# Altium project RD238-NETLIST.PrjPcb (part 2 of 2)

## Sheet 15.SchDoc
size 420 x 297 mm
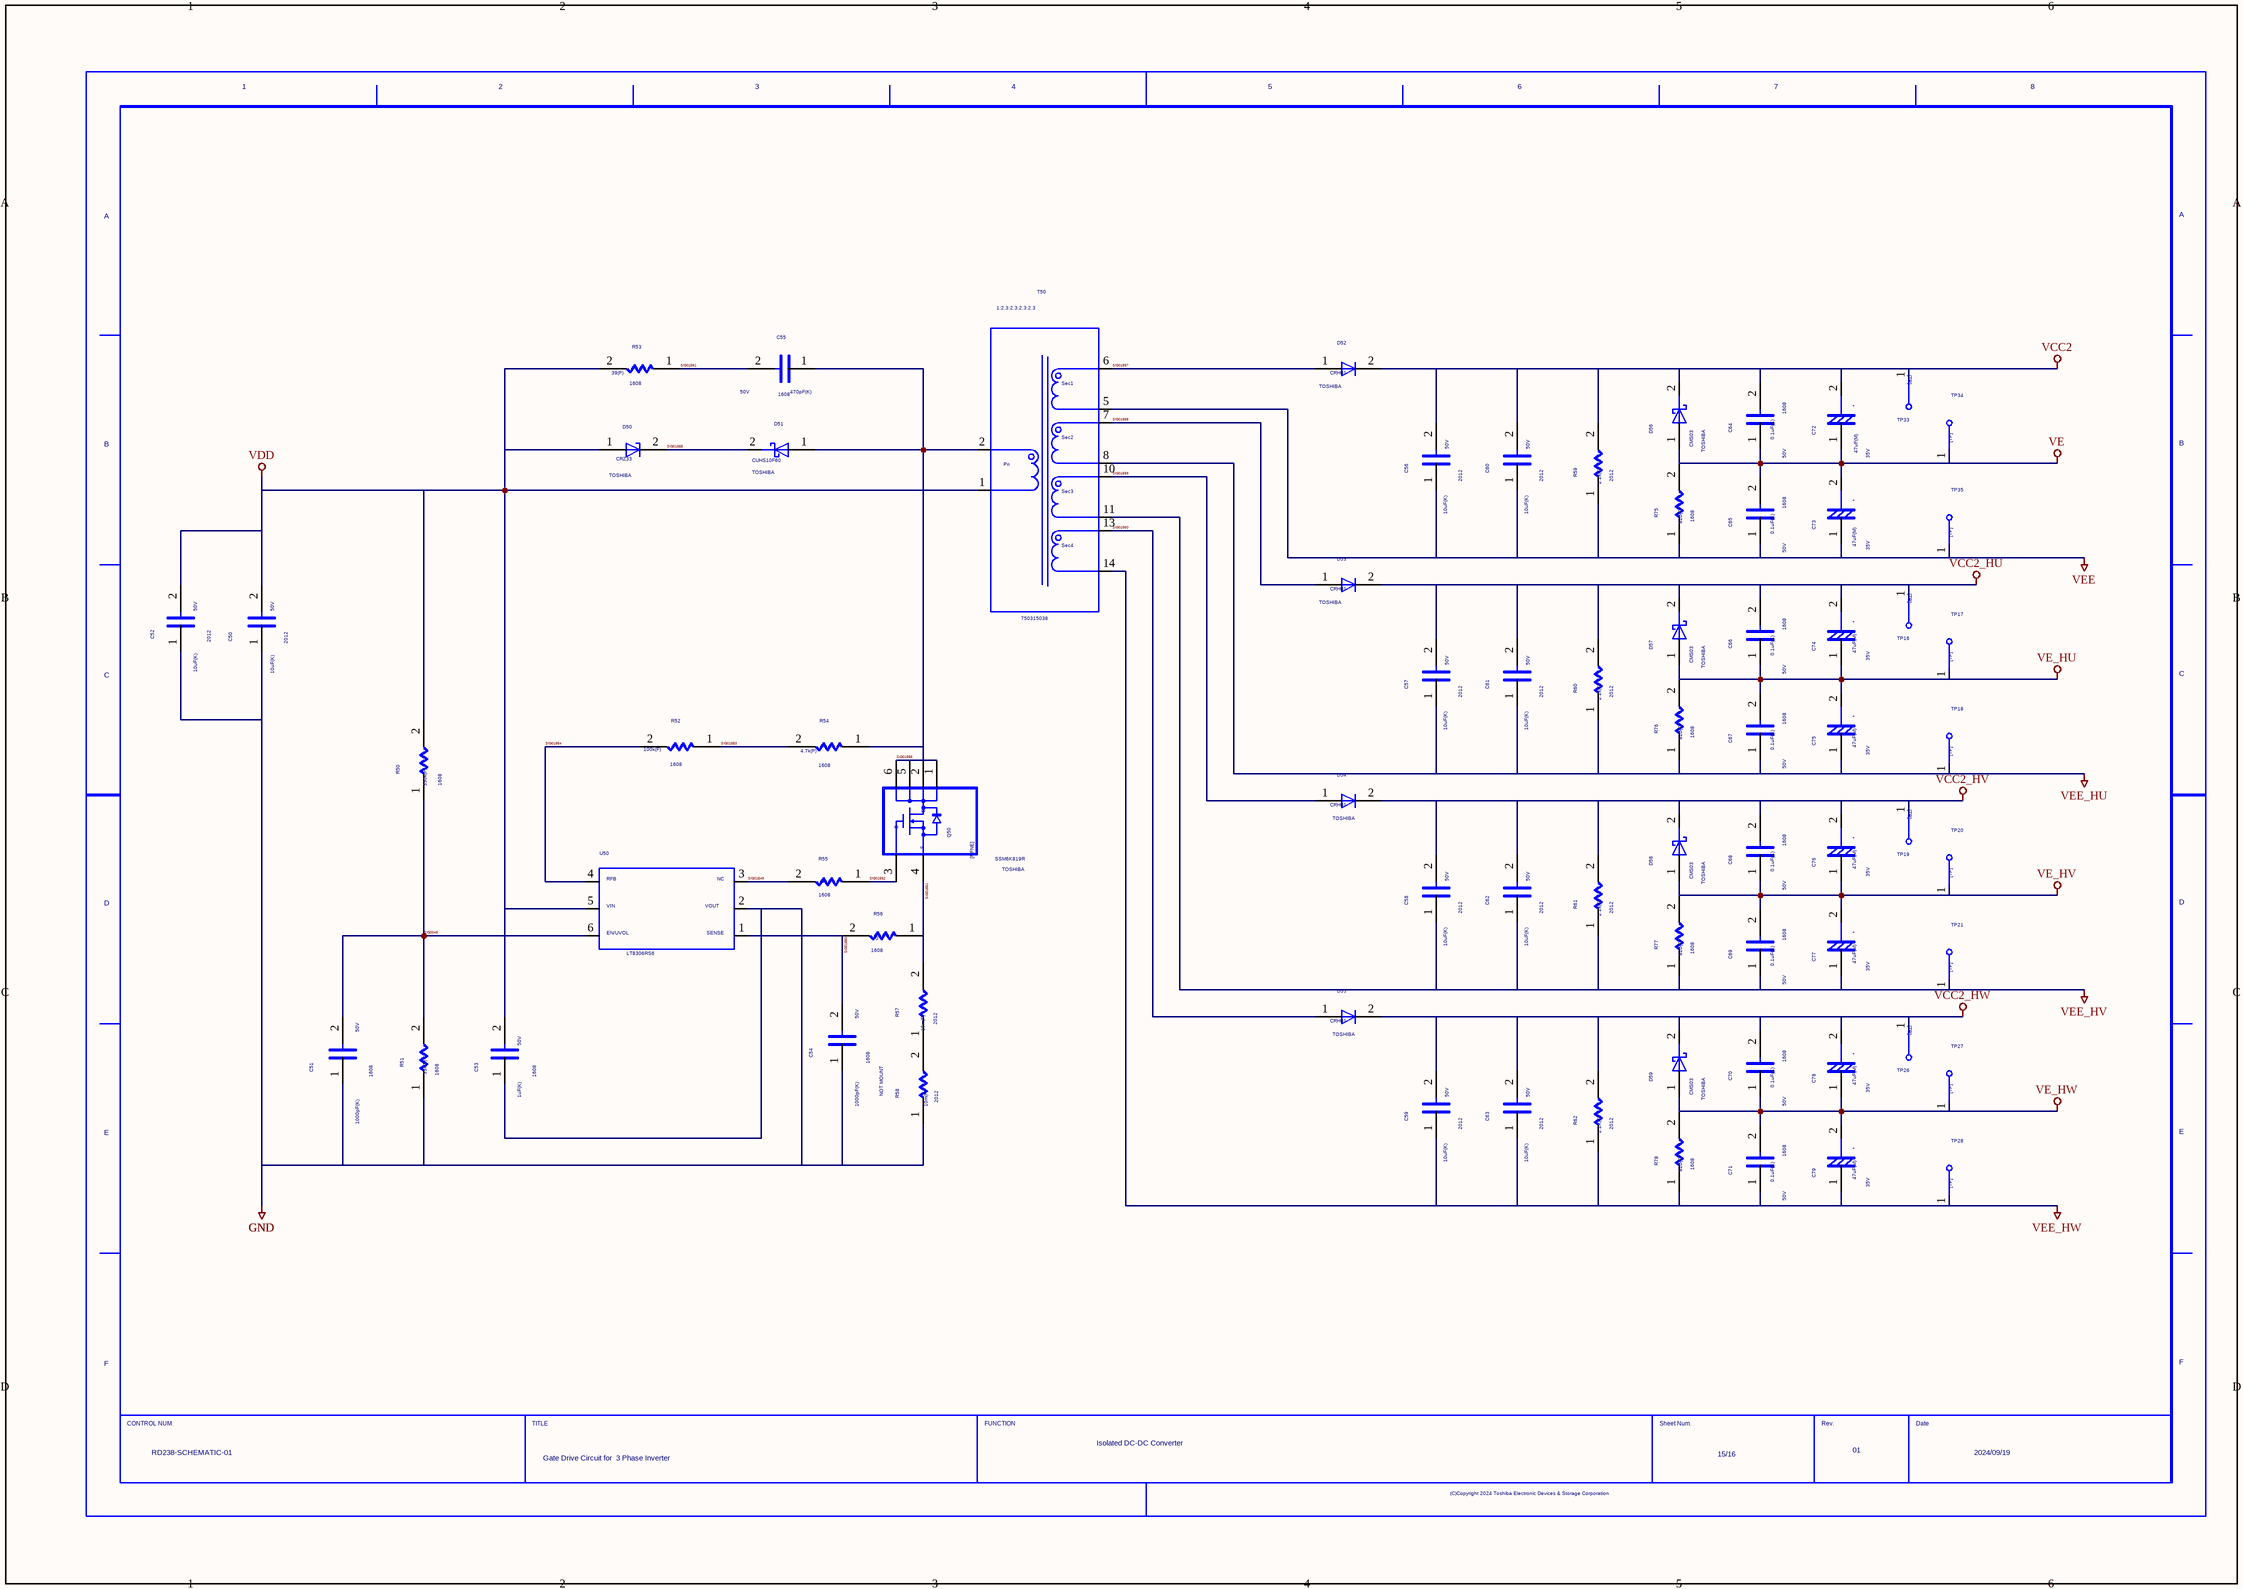
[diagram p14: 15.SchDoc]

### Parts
(Parts that share a designator on the sheet are numbered #1, #2 ... from top to bottom, then left to right.)
C50  VAL1: 10uF(K)  VAL2: 50V  SIZECODESMD: 2012  (hidden comment: C)
C51  VAL1: 1000pF(K)  VAL2: 50V  SIZECODESMD: 1608  (hidden comment: C)
C52  VAL1: 10uF(K)  VAL2: 50V  SIZECODESMD: 2012  (hidden comment: C)
C53  VAL1: 1uF(K)  VAL2: 50V  SIZECODESMD: 1608  (hidden comment: C)
C54  NOTMOUNT: NOT MOUNT  VAL1: 1000pF(K)  VAL2: 50V  SIZECODESMD: 1608  (hidden comment: C)
C55  VAL1: 470pF(K)  VAL2: 50V  SIZECODESMD: 1608  (hidden comment: C)
C56  VAL1: 10uF(K)  VAL2: 50V  SIZECODESMD: 2012  (hidden comment: C)
C57  VAL1: 10uF(K)  VAL2: 50V  SIZECODESMD: 2012  (hidden comment: C)
C58  VAL1: 10uF(K)  VAL2: 50V  SIZECODESMD: 2012  (hidden comment: C)
C59  VAL1: 10uF(K)  VAL2: 50V  SIZECODESMD: 2012  (hidden comment: C)
C60  VAL1: 10uF(K)  VAL2: 50V  SIZECODESMD: 2012  (hidden comment: C)
C61  VAL1: 10uF(K)  VAL2: 50V  SIZECODESMD: 2012  (hidden comment: C)
C62  VAL1: 10uF(K)  VAL2: 50V  SIZECODESMD: 2012  (hidden comment: C)
C63  VAL1: 10uF(K)  VAL2: 50V  SIZECODESMD: 2012  (hidden comment: C)
C64  VAL1: 0.1uF(K)  VAL2: 50V  SIZECODESMD: 1608  (hidden comment: C)
C65  VAL1: 0.1uF(K)  VAL2: 50V  SIZECODESMD: 1608  (hidden comment: C)
C66  VAL1: 0.1uF(K)  VAL2: 50V  SIZECODESMD: 1608  (hidden comment: C)
C67  VAL1: 0.1uF(K)  VAL2: 50V  SIZECODESMD: 1608  (hidden comment: C)
C68  VAL1: 0.1uF(K)  VAL2: 50V  SIZECODESMD: 1608  (hidden comment: C)
C69  VAL1: 0.1uF(K)  VAL2: 50V  SIZECODESMD: 1608  (hidden comment: C)
C70  VAL1: 0.1uF(K)  VAL2: 50V  SIZECODESMD: 1608  (hidden comment: C)
C71  VAL1: 0.1uF(K)  VAL2: 50V  SIZECODESMD: 1608  (hidden comment: C)
C72  VAL1: 47uF(M)  VAL2: 35V  (hidden comment: C_2)
C73  VAL1: 47uF(M)  VAL2: 35V  (hidden comment: C_2)
C74  VAL1: 47uF(M)  VAL2: 35V  (hidden comment: C_2)
C75  VAL1: 47uF(M)  VAL2: 35V  (hidden comment: C_2)
C76  VAL1: 47uF(M)  VAL2: 35V  (hidden comment: C_2)
C77  VAL1: 47uF(M)  VAL2: 35V  (hidden comment: C_2)
C78  VAL1: 47uF(M)  VAL2: 35V  (hidden comment: C_2)
C79  VAL1: 47uF(M)  VAL2: 35V  (hidden comment: C_2)
D50  USERCOMPTEXT3: TOSHIBA  VAL3: CRZ33  (hidden comment: ZD3)
D51  USERCOMPTEXT3: TOSHIBA  VAL3: CUHS10F60  (hidden comment: SBD1)
D52  USERCOMPTEXT3: TOSHIBA  VAL3: CRH01  (hidden comment: D1)
D53  USERCOMPTEXT3: TOSHIBA  VAL3: CRH01  (hidden comment: D1)
D54  USERCOMPTEXT3: TOSHIBA  VAL3: CRH01  (hidden comment: D1)
D55  USERCOMPTEXT3: TOSHIBA  VAL3: CRH01  (hidden comment: D1)
D56  USERCOMPTEXT3: TOSHIBA  VAL3: CMS03  (hidden comment: SBD1)
D57  USERCOMPTEXT3: TOSHIBA  VAL3: CMS03  (hidden comment: SBD1)
D58  USERCOMPTEXT3: TOSHIBA  VAL3: CMS03  (hidden comment: SBD1)
D59  USERCOMPTEXT3: TOSHIBA  VAL3: CMS03  (hidden comment: SBD1)
Q50  USERCOMPTEXT3: TOSHIBA  VAL3: SSM6K819R  (hidden comment: MFNE)
R50  VAL1: 330k(F)  SIZECODESMD: 1608  (hidden comment: R)
R51  VAL1: 33k(F)  SIZECODESMD: 1608  (hidden comment: R)
R52  VAL1: 100k(F)  SIZECODESMD: 1608  (hidden comment: R)
R53  VAL1: 39(F)  SIZECODESMD: 1608  (hidden comment: R)
R54  VAL1: 4.7k(F)  SIZECODESMD: 1608  (hidden comment: R)
R55  VAL1: 0  SIZECODESMD: 1608  (hidden comment: R)
R56  VAL1: 0  SIZECODESMD: 1608  (hidden comment: R)
R57  VAL1: 10m(F)  SIZECODESMD: 2012  (hidden comment: R)
R58  VAL1: 10m(F)  SIZECODESMD: 2012  (hidden comment: R)
R59  VAL1: 2.2k(F)  SIZECODESMD: 2012  (hidden comment: R)
R60  VAL1: 2.2k(F)  SIZECODESMD: 2012  (hidden comment: R)
R61  VAL1: 2.2k(F)  SIZECODESMD: 2012  (hidden comment: R)
R62  VAL1: 2.2K(F)  SIZECODESMD: 2012  (hidden comment: R)
R75  VAL1: 820(F)  SIZECODESMD: 1608  (hidden comment: R)
R76  VAL1: 820(F)  SIZECODESMD: 1608  (hidden comment: R)
R77  VAL1: 820(F)  SIZECODESMD: 1608  (hidden comment: R)
R78  VAL1: 820(F)  SIZECODESMD: 1608  (hidden comment: R)
T50  VAL1: 1:2.3:2.3:2.3:2.3  (hidden comment: 750315038)
TP16  TP  (value not drawn)
TP17  TP  (value not drawn)
TP18  TP  (value not drawn)
TP19  TP  (value not drawn)
TP20  TP  (value not drawn)
TP21  TP  (value not drawn)
TP26  TP  (value not drawn)
TP27  TP  (value not drawn)
TP28  TP  (value not drawn)
TP33  TP  (value not drawn)
TP34  TP  (value not drawn)
TP35  TP  (value not drawn)
U50  COMPONENTNAME: LT8306RS6  (hidden comment: TCR1HF50B)
U?#15  DATE: 2024/09/19  DRAWINGNUMBER: RD238-SCHEMATIC-01  TITLE: Gate Drive Circuit for / 3 Phase Inverter  FUNCTION: Isolated DC-DC Converter  SHEETNUMBER: 15/16  REVISION: 01  (hidden comment: WAKU_DEF100)

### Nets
GND: C50.1 C51.1 C52.1 C53.1 C54.1 R51.1 R58.1 U50.2
VCC2: C56.2 C60.2 C64.2 C72.2 D52.2 D56.2 R59.2 TP33.1
VCC2_HU: C57.2 C61.2 C66.2 C74.2 D53.2 D57.2 R60.2 TP16.1
VCC2_HV: C58.2 C62.2 C68.2 C76.2 D54.2 D58.2 R61.2 TP19.1
VCC2_HW: C59.2 C63.2 C70.2 C78.2 D55.2 D59.2 R62.2 TP26.1
VDD: C50.2 C52.2 C53.2 D50.1 R50.2 R53.2 T50.1 U50.5
VE: C64.1 C65.2 C72.1 C73.2 D56.1 R75.2 TP34.1
VE_HU: C66.1 C67.2 C74.1 C75.2 D57.1 R76.2 TP17.1
VE_HV: C68.1 C69.2 C76.1 C77.2 D58.1 R77.2 TP20.1
VE_HW: C70.1 C71.2 C78.1 C79.2 D59.1 R78.2 TP27.1
VEE: C56.1 C60.1 C65.1 C73.1 R59.1 R75.1 T50.5 TP35.1
VEE_HU: C57.1 C61.1 C67.1 C75.1 R60.1 R76.1 T50.8 TP18.1
VEE_HV: C58.1 C62.1 C69.1 C77.1 R61.1 R77.1 T50.11 TP21.1
VEE_HW: C59.1 C63.1 C71.1 C79.1 R62.1 R78.1 T50.14 TP28.1
SIG0045: C51.2 R50.1 R51.2 U50.6
SIG01549: R55.2 U50.3
SIG01550: C54.2 R56.2 U50.1
SIG01551: Q50.4 R56.1 R57.2
SIG01552: Q50.3 R55.1
SIG01553: R52.1 R54.2
SIG01554: R52.2 U50.4
SIG01555: D50.2 D51.2
SIG01556: C55.1 D51.1 Q50.1 Q50.2 Q50.5 Q50.6 R54.1 T50.2
SIG01557: D52.1 T50.6
SIG01558: D53.1 T50.7
SIG01559: D54.1 T50.10
SIG01560: D55.1 T50.13
SIG01561: C55.2 R53.1
NetR57_1: R57.1 R58.2

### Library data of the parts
C50-C71 = C: OriginalSymbolOrigin: (2540,7620)
C72-C79 = C_2: TIME: 11:26:26; UPDATEUSER: sptcae09; SAVECOUNT: 1; OriginalSymbolOrigin: (2540,10160); COMP: C
D50 = ZD3: SAVEAREA0: -4630,-153,17114,13055; TIME: 14:49:55; UPDATEUSER: w20165dm; UPDATETIME: 14:57:31; SAVECOUNT: 8; OriginalSymbolOrigin: (5080,5080)
D51 D56-D59 = SBD1: SAVEAREA0: -4630,-153,17114,13055; TIME: 14:49:55; UPDATEUSER: w20165dm; UPDATETIME: 13:53:59; SAVECOUNT: 10; OriginalSymbolOrigin: (5080,5080)
D52-D55 = D1: SAVEAREA0: -225,-91,12804,7836; SAVECOUNT: 4; TIME: 14:49:55; UPDATEUSER: w20165dm; UPDATETIME: 14:35:38; OriginalSymbolOrigin: (5080,5080)
Q50 = MFNE: SAVECOUNT: 14; SAVEAREA0: -7120,-295,29516,23636; OriginalSymbolOrigin: (5080,20320)
R50 R51 R54 = R: VAL2: 0.1W; OriginalSymbolOrigin: (5080,5080)
R52 = R: VAL2: 100mW; OriginalSymbolOrigin: (5080,5080)
R53 R75-R78 = R: VAL2: 0.125W; OriginalSymbolOrigin: (5080,5080)
R55 R56 = R: VAL2: 1A; OriginalSymbolOrigin: (5080,5080)
R57-R62 = R: VAL2: 0.5W; OriginalSymbolOrigin: (5080,5080)
T50 = 750315038: SAVECOUNT: 24; SAVEAREA0: -14227,-538,38802,29317; TIME: 11:19:06; UPDATEUSER: t5459927; UPDATETIME: 08:42:27; OriginalSymbolOrigin: (2540,55880)
TP16-TP21 TP26-TP28 TP33-TP35 = TP_Dup1: TIME: 16:12:21; UPDATEUSER: fukuda-y; UPDATETIME: 16:18:11; SAVECOUNT: 2; SAVEAREA0: -242,-92,12810,7836; OriginalSymbolOrigin: (0,7620); VAL1: SWB; COMP: TEST_PAD
U50 = LT8306: MANUFACTURER: toshiba; ORDER: $pOrder; 特性1: 36 V; 特性2: 150mA; DESCRIPTION-A: LDO; TIME: 08:52:33; UPDATEUSER: sptcae09; UPDATETIME: 10:47:12; SAVECOUNT: 7; OriginalSymbolOrigin: (2540,17780); COMP: U
U?#15 = WAKU_DEF100: SAVEAREA0: 185750,-43960,448537,75779; TIME: 14:30:25; UPDATEUSER: t5459927; UPDATETIME: 10:22:18; SAVECOUNT: 9; OriginalSymbolOrigin: (10160,284480); SHTSAVECOUNT: 54

## Sheet 16.SchDoc
size 420 x 297 mm
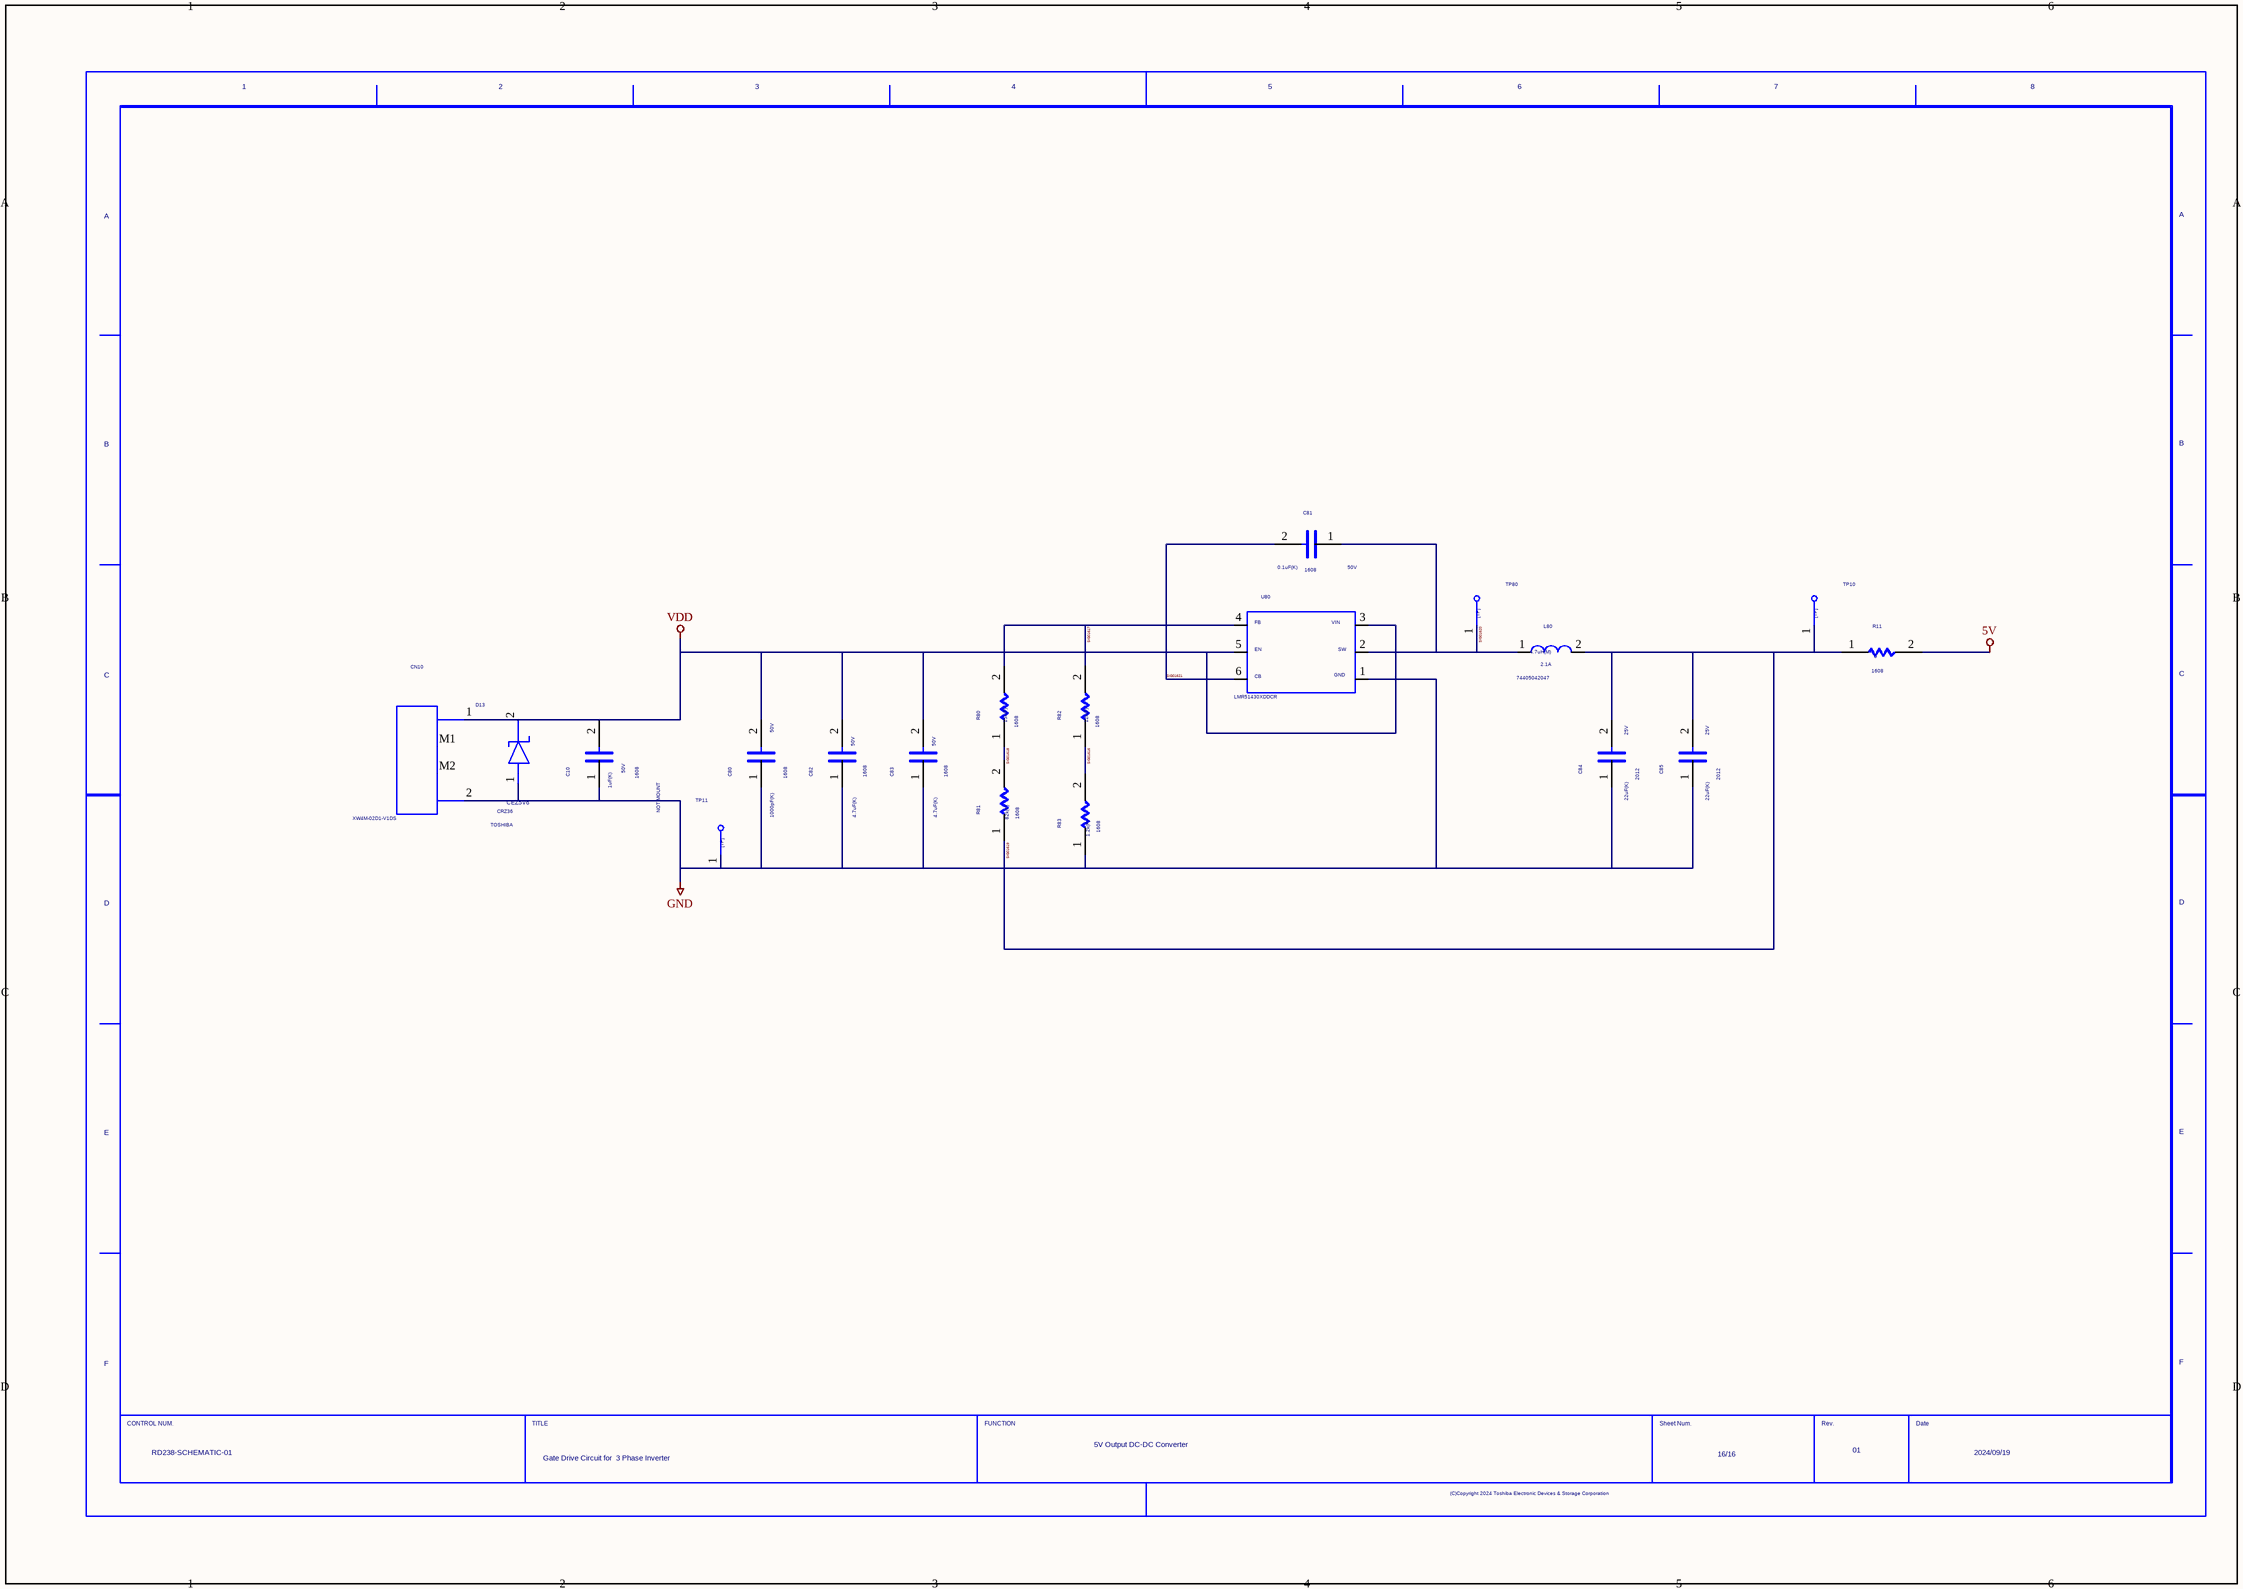
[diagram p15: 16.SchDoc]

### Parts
(Parts that share a designator on the sheet are numbered #1, #2 ... from top to bottom, then left to right.)
C10  NOTMOUNT: NOT MOUNT  VAL1: 1uF(K)  VAL2: 50V  SIZECODESMD: 1608  (hidden comment: C)
C80  VAL1: 1000pF(K)  VAL2: 50V  SIZECODESMD: 1608  (hidden comment: C)
C81  VAL1: 0.1uF(K)  VAL2: 50V  SIZECODESMD: 1608  (hidden comment: C)
C82  VAL1: 4.7uF(K)  VAL2: 50V  SIZECODESMD: 1608  (hidden comment: C)
C83  VAL1: 4.7uF(K)  VAL2: 50V  SIZECODESMD: 1608  (hidden comment: C)
C84  VAL1: 22uF(K)  VAL2: 25V  SIZECODESMD: 2012  (hidden comment: C)
C85  VAL1: 22uF(K)  VAL2: 25V  SIZECODESMD: 2012  (hidden comment: C)
CN10  VAL3: XW4M-02D1-V1DS  (hidden comment: XW4M-02DI-VIDS)
D13  CEZ5V6  VAL3: CRZ36  USERCOMPTEXT3: TOSHIBA
L80  VAL3: 74405042047  VAL2: 2.1A  VAL1: 4.7uH(M)  (hidden comment: L)
R11  VAL1: 0  SIZECODESMD: 1608  (hidden comment: R)
R80  VAL1: 15k(F)  SIZECODESMD: 1608  (hidden comment: R)
R81  VAL1: 82k(F)  SIZECODESMD: 1608  (hidden comment: R)
R82  VAL1: 12k(F)  SIZECODESMD: 1608  (hidden comment: R)
R83  VAL1: 1.2k(F)  SIZECODESMD: 1608  (hidden comment: R)
TP10  TP  (value not drawn)
TP11  TP  (value not drawn)
TP80  TP  (value not drawn)
U80  TCR1HF50B  (value not drawn)
U?#16  DATE: 2024/09/19  DRAWINGNUMBER: RD238-SCHEMATIC-01  TITLE: Gate Drive Circuit for / 3 Phase Inverter  FUNCTION: 5V Output DC-DC Converter  SHEETNUMBER: 16/16  REVISION: 01  (hidden comment: WAKU_DEF100)

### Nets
5V: R11.2
GND: C10.1 C80.1 C82.1 C83.1 C84.1 C85.1 CN10.2 D13.1(ANODE) R83.1 TP11.1 U80.1
VDD: C10.2 C80.2 C82.2 C83.2 CN10.1 D13.2(CATHODE) U80.3 U80.5
SIG01616: R82.1 R83.2
SIG01617: R80.2 R82.2 U80.4
SIG01618: R80.1 R81.2
SIG01619: C84.2 C85.2 L80.2 R11.1 R81.1 TP10.1
SIG01620: C81.1 L80.1 TP80.1 U80.2
SIG01621: C81.2 U80.6

Not connected (* = marked no-connect by the designer): CN10 M1(empty-1) M2(empty-2)

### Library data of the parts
C10 C80-C85 = C: OriginalSymbolOrigin: (2540,7620)
CN10 = XW4M-02DI-VIDS: SAVECOUNT: 28; SAVEAREA0: -772,-286,43980,28213; TIME: 16:55:50; UPDATEUSER: t5459927; UPDATETIME: 14:55:33; OriginalSymbolOrigin: (2540,22860); COMP: CN
D13 = CEZ5V6_D500#1: ORDER: $pOrder; 特性1: 5.6V; 特性2: 5mA; DESCRIPTION-A: DIODE Zener, 5.6V, 5mA, 150mW; TIME: 08:52:39; UPDATEUSER: sptcae13; SAVECOUNT: 1; OriginalSymbolOrigin: (0,-2540); CaptureCellPackProp: CEZ5V6_D500##1
L80 = L: SAVECOUNT: 24; SAVEAREA0: -14227,-538,38802,29317; TIME: 11:19:06; UPDATEUSER: sptcae09; UPDATETIME: 15:04:42; OriginalSymbolOrigin: (2540,5080)
R11 = R: as R55 on sheet 15
R80-R83 = R: as R52 on sheet 15
TP10 TP11 TP80 = TP_Dup1: as TP16-TP21 on sheet 15
U80 = LMR51430XDDCR: MANUFACTURER: toshiba; ORDER: $pOrder; 特性1: 36 V; 特性2: 150mA; DESCRIPTION-A: LDO; TIME: 08:52:33; UPDATEUSER: sptcae09; UPDATETIME: 14:43:51; SAVECOUNT: 8; OriginalSymbolOrigin: (2540,17780); COMP: U
U?#16 = WAKU_DEF100: SAVEAREA0: 185750,-43960,448537,75779; TIME: 14:30:25; UPDATEUSER: t5459927; UPDATETIME: 10:22:38; SAVECOUNT: 9; OriginalSymbolOrigin: (10160,284480); SHTSAVECOUNT: 34

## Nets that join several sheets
5V: 1 (7 pins), 2 (C222.2 C232.2 R242.2 U202.5), 3 (C223.2 C233.2 R243.2 U203.5), 4 (C224.2 C234.2 R244.2 U204.5), 5 (C225.2 C235.2 R245.2 U205.5), 6 (C226.2 C236.2 R246.2 U206.5), 7 (C227.2 C237.2 R247.2 U207.5), 8 (C311.1 U301.2), 9 (C312.1 U302.2), 10 (C313.1 U303.2), 11 (C314.1 U304.2), 12 (C315.1 U305.2), 13 (C316.1 U306.2), 14 (C317.1 U307.2), 16 (R11.2)
EN: 1 (CN11.13 D12.1 R13.2 R221.2), 2 (R222.2), 3 (R223.2), 4 (R224.2), 5 (R225.2), 6 (R226.2), 7 (R227.2)
FAULT: 1 (CN11.15 D11.1 R12.2), 8 (C301.1 U301.3), 9 (C302.1 U302.3), 10 (C303.1 U303.3), 11 (C304.1 U304.3), 12 (C305.1 U305.3), 13 (C306.1 U306.3), 14 (C307.1 U307.3)
GND: 1 (25 pins), 2 (9 pins), 3 (9 pins), 4 (9 pins), 5 (9 pins), 6 (9 pins), 7 (9 pins), 8 (C301.2 C311.2 U301.1 U301.4), 9 (C302.2 C312.2 U302.1 U302.4), 10 (C303.2 C313.2 U303.1 U303.4), 11 (C304.2 C314.2 U304.1 U304.4), 12 (C305.2 C315.2 U305.1 U305.4), 13 (C306.2 C316.2 U306.1 U306.4), 14 (C307.2 C317.2 U307.1 U307.4), 15 (8 pins), 16 (11 pins)
VCC2: 11 (5 pins), 12 (5 pins), 13 (5 pins), 14 (5 pins), 15 (8 pins)
VCC2_HU: 8 (5 pins), 15 (8 pins)
VCC2_HV: 9 (5 pins), 15 (8 pins)
VCC2_HW: 10 (5 pins), 15 (8 pins)
VDD: 15 (8 pins), 16 (8 pins)
VE: 11 (11 pins), 12 (11 pins), 13 (11 pins), 14 (11 pins), 15 (7 pins)
VE_HU: 8 (11 pins), 15 (7 pins)
VE_HV: 9 (11 pins), 15 (7 pins)
VE_HW: 10 (11 pins), 15 (7 pins)
VEE: 11 (6 pins), 12 (6 pins), 13 (6 pins), 14 (6 pins), 15 (8 pins)
VEE_HU: 8 (6 pins), 15 (8 pins)
VEE_HV: 9 (6 pins), 15 (8 pins)
VEE_HW: 10 (6 pins), 15 (8 pins)
ANODE_BR: 7 (C247.2 R247.1 R257.2 TP36.1), 14 (U307.6 U307.7)
ANODE_HU: 1 (C241.2 R241.1 R251.2 TP14.1), 8 (U301.6 U301.7)
ANODE_HV: 2 (C242.2 R242.1 R252.2 TP22.1), 9 (U302.6 U302.7)
ANODE_HW: 3 (C243.2 R243.1 R253.2 TP29.1), 10 (U303.6 U303.7)
ANODE_LU: 4 (C244.2 R244.1 R254.2 TP12.1), 11 (U304.6 U304.7)
ANODE_LV: 5 (C245.2 R245.1 R255.2 TP23.1), 12 (U305.6 U305.7)
ANODE_LW: 6 (C246.2 R246.1 R256.2 TP31.1), 13 (U306.6 U306.7)
CATHODE_BR: 7 (C247.1 Q207.3 R257.1 TP37.1), 14 (U307.5 U307.8)
CATHODE_HU: 1 (C241.1 Q201.3 R251.1 TP15.1), 8 (U301.5 U301.8)
CATHODE_HV: 2 (C242.1 Q202.3 R252.1 TP24.1), 9 (U302.5 U302.8)
CATHODE_HW: 3 (C243.1 Q203.3 R253.1 TP30.1), 10 (U303.5 U303.8)
CATHODE_LU: 4 (C244.1 Q204.3 R254.1 TP13.1), 11 (U304.5 U304.8)
CATHODE_LV: 5 (C245.1 Q205.3 R255.1 TP25.1), 12 (U305.5 U305.8)
CATHODE_LW: 6 (C246.1 Q206.3 R256.1 TP32.1), 13 (U306.5 U306.8)
IN_BR: 1 (CN11.17), 7 (D207.1 R207.2 R217.2)
IN_HV: 1 (CN11.3), 2 (D202.1 R202.2 R212.2)
IN_HW: 1 (CN11.5), 3 (D203.1 R203.2 R213.2)
IN_LU: 1 (CN11.7), 4 (D204.1 R204.2 R214.2)
IN_LV: 1 (CN11.9), 5 (D205.1 R205.2 R215.2)
IN_LW: 1 (CN11.11), 6 (D206.1 R206.2 R216.2)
